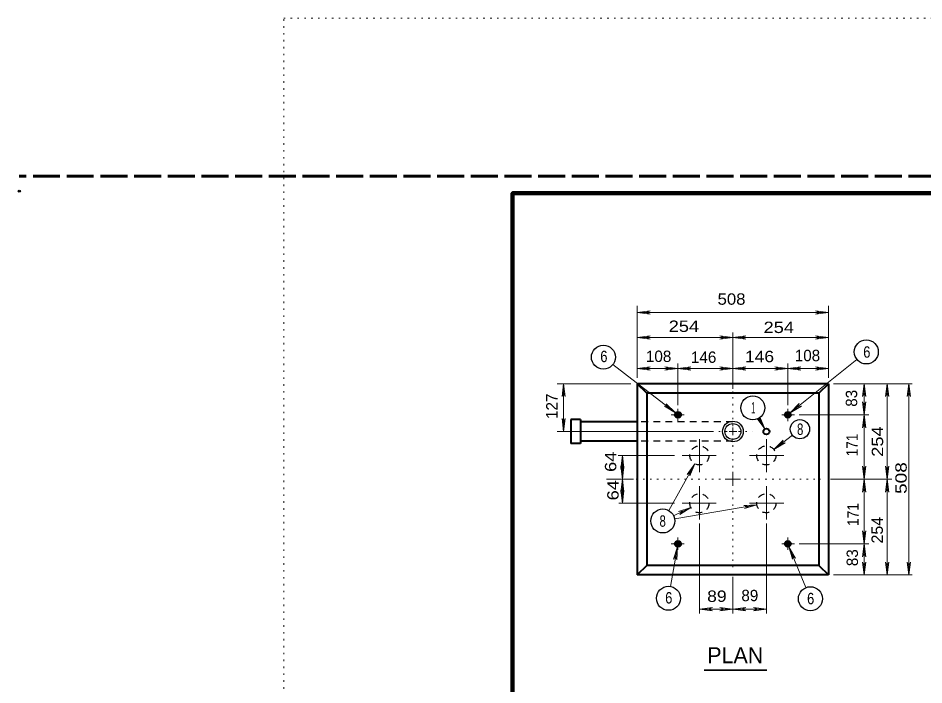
# Model space of a CAD drawing. Extents: x 312583 to 312854, y 144419 to 144597.
# Drawn here: x 312583.5 to 312644, y 144552.2 to 144596.8 of the extents above; entities that cross this region are included whole.
import ezdxf
from ezdxf.enums import TextEntityAlignment as Align

# ---------------------------------------------------------------- set-up
doc = ezdxf.new("R2010")
doc.units = 0
doc.header["$LTSCALE"] = 0.3
doc.header["$PDMODE"] = 32
doc.header["$PDSIZE"] = 0.15
for name, pattern in [('DOTTED', [1.5, 0.3, -1.2]), ('LONG_DASHED', [7.5, 6, -1.5]), ('SHORT_DASHED', [2.7, 1.5, -1.2])]:
    doc.linetypes.add(name, pattern=pattern)
for name, color, linetype, lineweight in [('1', 7, 'Continuous', 25), ('2', 7, 'Continuous', 13), ('63', 7, 'DOTTED', 13)]:
    doc.layers.add(name, color=color, linetype=linetype, lineweight=lineweight)

msp = doc.modelspace()

# ---------------------------------------------------------------- linework, layer by layer
at = {"layer": '1', "linetype": 'LONG_DASHED', "lineweight": 60}
msp.add_line((312851.75, 144586.2246), (312583.526, 144586.2246), dxfattribs=at)
at = {"layer": '1', "lineweight": 40}
for p, q in [((312637.6103, 144572.3614), (312624.83, 144572.3614)), ((312624.83, 144572.3614), (312624.83, 144559.581)), ((312625.4663, 144571.725), (312624.83, 144572.3614)), ((312637.6103, 144572.3614), (312636.9663, 144571.725)), ((312637.6103, 144572.3614), (312637.6103, 144559.581)), ((312636.9663, 144571.725), (312636.9663, 144560.225)), ((312620.3986, 144569.9694), (312620.3986, 144568.367)), ((312621.035, 144569.9694), (312620.3986, 144569.9694)), ((312621.035, 144569.9694), (312621.035, 144568.367)), ((312624.83, 144569.8084), (312621.035, 144569.8084)), ((312621.035, 144568.367), (312620.3986, 144568.367)), ((312624.83, 144568.528), (312621.035, 144568.528)), ((312625.4663, 144560.225), (312624.83, 144559.581)), ((312636.9663, 144560.225), (312625.4663, 144560.225)), ((312636.9663, 144560.225), (312637.6103, 144559.581)), ((312637.6103, 144559.581), (312624.83, 144559.581))]:
    msp.add_line(p, q, dxfattribs=at)
at = {"layer": '1', "linetype": 'SHORT_DASHED'}
for p, q in [((312631.2163, 144569.8084), (312624.83, 144569.8084)), ((312631.2163, 144568.528), (312624.83, 144568.528))]:
    msp.add_line(p, q, dxfattribs=at)
at = {"layer": '1', "lineweight": 158}
msp.add_lwpolyline([(312616.5, 144423.1446), (312616.5, 144585.0846), (312849, 144585.0846)], dxfattribs=at)
at = {"layer": '1', "lineweight": 40}
msp.add_lwpolyline([(312636.9663, 144571.725), (312625.4663, 144571.725), (312625.4663, 144560.225)], dxfattribs=at)
for centre, radius in [((312627.5452, 144570.285), 0.1996), ((312627.5452, 144570.285), 0.1597), ((312627.5452, 144570.285), 0.1278), ((312627.5452, 144570.285), 0.1022), ((312627.5452, 144570.285), 0.0818), ((312627.5452, 144570.285), 0.0654), ((312627.5452, 144570.285), 0.0523), ((312627.5452, 144570.285), 0.0419), ((312627.5452, 144570.285), 0.0335), ((312634.8925, 144570.285), 0.1996), ((312634.8925, 144570.285), 0.1597), ((312634.8925, 144570.285), 0.1278), ((312634.8925, 144570.285), 0.1022), ((312634.8925, 144570.285), 0.0818), ((312634.8925, 144570.285), 0.0654), ((312634.8925, 144570.285), 0.0523), ((312634.8925, 144570.285), 0.0419), ((312634.8925, 144570.285), 0.0335), ((312633.455, 144569.1669), 0.1996), ((312627.5452, 144561.66), 0.1996), ((312627.5452, 144561.66), 0.1597), ((312627.5452, 144561.66), 0.1278), ((312627.5452, 144561.66), 0.1022), ((312627.5452, 144561.66), 0.0818), ((312627.5452, 144561.66), 0.0654), ((312627.5452, 144561.66), 0.0523), ((312627.5452, 144561.66), 0.0419), ((312627.5452, 144561.66), 0.0335), ((312634.8925, 144561.66), 0.1996), ((312634.8925, 144561.66), 0.1597), ((312634.8925, 144561.66), 0.1278), ((312634.8925, 144561.66), 0.1022), ((312634.8925, 144561.66), 0.0818), ((312634.8925, 144561.66), 0.0654), ((312634.8925, 144561.66), 0.0523), ((312634.8925, 144561.66), 0.0419), ((312634.8925, 144561.66), 0.0335)]:
    msp.add_circle(centre, radius, dxfattribs=at)
at = {"layer": '1'}
for radius in [0.6919, 0.5322]:
    msp.add_circle((312631.2189, 144569.1669), radius, dxfattribs=at)
at = {"layer": '1', "linetype": 'SHORT_DASHED'}
for centre in [(312628.9827, 144567.5697), (312633.455, 144567.5697), (312628.9827, 144564.3753), (312633.455, 144564.3753)]:
    msp.add_circle(centre, 0.6389, dxfattribs=at)
at = {"layer": '1'}
msp.add_point((312583.526, 144585.2246), dxfattribs=at)
at = {"layer": '2'}
for p, q in [((312624.83, 144572.7524), (312624.83, 144577.5517)), ((312637.6103, 144572.7524), (312637.6103, 144577.5517)), ((312624.83, 144577.1224), (312625.6963, 144577.2297)), ((312637.6103, 144577.1224), (312624.83, 144577.1224)), ((312624.83, 144577.1224), (312625.6963, 144577.015)), ((312625.6963, 144577.2297), (312625.4203, 144577.1224)), ((312625.6963, 144577.015), (312625.4203, 144577.1224)), ((312636.744, 144577.2297), (312637.02, 144577.1224)), ((312637.6103, 144577.1224), (312636.744, 144577.2297)), ((312636.744, 144577.015), (312637.02, 144577.1224)), ((312637.6103, 144577.1224), (312636.744, 144577.015)), ((312624.83, 144575.451), (312625.6963, 144575.5584)), ((312625.6963, 144575.5584), (312625.4203, 144575.451)), ((312630.35, 144575.5584), (312630.626, 144575.451)), ((312631.2163, 144575.451), (312630.35, 144575.5584)), ((312631.2163, 144572.0164), (312631.2163, 144575.773)), ((312631.2163, 144575.451), (312632.0826, 144575.5584)), ((312632.0826, 144575.5584), (312631.8066, 144575.451)), ((312636.744, 144575.5584), (312637.02, 144575.451)), ((312637.6103, 144575.451), (312636.744, 144575.5584)), ((312624.83, 144575.451), (312625.6963, 144575.3437)), ((312625.6963, 144575.3437), (312625.4203, 144575.451)), ((312630.35, 144575.3437), (312630.626, 144575.451)), ((312631.2163, 144575.451), (312630.35, 144575.3437)), ((312631.2163, 144575.451), (312632.0826, 144575.3437)), ((312632.0826, 144575.3437), (312631.8066, 144575.451)), ((312636.744, 144575.3437), (312637.02, 144575.451)), ((312637.6103, 144575.451), (312636.744, 144575.3437)), ((312627.544, 144570.9354), (312627.544, 144573.703)), ((312634.8963, 144570.9354), (312634.8963, 144573.703)), ((312635.0496, 144570.4064), (312639.5116, 144573.979)), ((312623.2046, 144573.6417), (312627.3906, 144570.4064)), ((312624.83, 144573.3734), (312625.6963, 144573.4807)), ((312627.544, 144573.3734), (312624.83, 144573.3734)), ((312624.83, 144573.3734), (312625.6963, 144573.266)), ((312625.6963, 144573.4807), (312625.4203, 144573.3734)), ((312625.6963, 144573.266), (312625.4203, 144573.3734)), ((312626.6776, 144573.4807), (312626.9536, 144573.3734)), ((312627.544, 144573.3734), (312626.6776, 144573.4807)), ((312626.6776, 144573.266), (312626.9536, 144573.3734)), ((312627.544, 144573.3734), (312626.6776, 144573.266)), ((312627.544, 144573.3734), (312628.4103, 144573.4807)), ((312631.2163, 144573.3734), (312627.544, 144573.3734)), ((312627.544, 144573.3734), (312628.4103, 144573.266)), ((312628.4103, 144573.4807), (312628.1343, 144573.3734)), ((312628.4103, 144573.266), (312628.1343, 144573.3734)), ((312630.35, 144573.4807), (312630.626, 144573.3734)), ((312631.2163, 144573.3734), (312630.35, 144573.4807)), ((312630.35, 144573.266), (312630.626, 144573.3734)), ((312631.2163, 144573.3734), (312630.35, 144573.266)), ((312631.2163, 144573.3734), (312632.0826, 144573.4807)), ((312631.2163, 144573.3734), (312632.0826, 144573.266)), ((312632.0826, 144573.4807), (312631.8066, 144573.3734)), ((312632.0826, 144573.266), (312631.8066, 144573.3734)), ((312634.03, 144573.4807), (312634.306, 144573.3734)), ((312634.8963, 144573.3734), (312634.03, 144573.4807)), ((312634.03, 144573.266), (312634.306, 144573.3734)), ((312634.8963, 144573.3734), (312634.03, 144573.266)), ((312634.8963, 144573.3734), (312635.7626, 144573.4807)), ((312634.8963, 144573.3734), (312635.7626, 144573.266)), ((312635.7626, 144573.4807), (312635.4866, 144573.3734)), ((312635.7626, 144573.266), (312635.4866, 144573.3734)), ((312636.744, 144573.4807), (312637.02, 144573.3734)), ((312637.6103, 144573.3734), (312636.744, 144573.4807)), ((312636.744, 144573.266), (312637.02, 144573.3734)), ((312637.6103, 144573.3734), (312636.744, 144573.266)), ((312624.4083, 144572.3614), (312619.471, 144572.3614)), ((312619.908, 144572.3614), (312619.8006, 144571.495)), ((312619.908, 144569.1644), (312619.908, 144572.3614)), ((312619.908, 144572.3614), (312620.0153, 144571.495)), ((312637.9476, 144572.3614), (312643.2073, 144572.3614)), ((312639.987, 144572.3614), (312639.8796, 144571.495)), ((312639.987, 144572.3614), (312640.0943, 144571.495)), ((312641.5356, 144572.3614), (312641.4283, 144571.495)), ((312641.5356, 144572.3614), (312641.643, 144571.495)), ((312642.9791, 144572.3614), (312642.8718, 144571.495)), ((312642.9791, 144559.581), (312642.9791, 144572.3614)), ((312642.9791, 144572.3614), (312643.0865, 144571.495)), ((312619.8006, 144571.495), (312619.908, 144571.771)), ((312620.0153, 144571.495), (312619.908, 144571.771)), ((312639.8796, 144571.495), (312639.987, 144571.771)), ((312640.0943, 144571.495), (312639.987, 144571.771)), ((312641.4283, 144571.495), (312641.5356, 144571.771)), ((312641.643, 144571.495), (312641.5356, 144571.771)), ((312642.8718, 144571.495), (312642.9791, 144571.771)), ((312643.0865, 144571.495), (312642.9791, 144571.771)), ((312626.6393, 144570.851), (312626.923, 144570.7667)), ((312627.3906, 144570.4064), (312626.6393, 144570.851)), ((312626.7696, 144571.0197), (312626.923, 144570.7667)), ((312627.3906, 144570.4064), (312626.7696, 144571.0197)), ((312627.544, 144569.8544), (312627.544, 144570.69)), ((312634.8963, 144569.8544), (312634.8963, 144570.69)), ((312635.0496, 144570.4064), (312635.6553, 144571.035)), ((312635.0496, 144570.4064), (312635.7933, 144570.8664)), ((312635.6553, 144571.035), (312635.5096, 144570.782)), ((312635.7933, 144570.8664), (312635.5096, 144570.782)), ((312639.8796, 144571.15), (312639.987, 144570.874)), ((312639.987, 144570.2837), (312639.8796, 144571.15)), ((312640.0943, 144571.15), (312639.987, 144570.874)), ((312639.987, 144570.2837), (312640.0943, 144571.15)), ((312619.8006, 144570.0307), (312619.908, 144569.7547)), ((312619.908, 144569.1644), (312619.8006, 144570.0307)), ((312620.0153, 144570.0307), (312619.908, 144569.7547)), ((312619.908, 144569.1644), (312620.0153, 144570.0307)), ((312627.958, 144570.2837), (312627.0993, 144570.2837)), ((312632.834, 144570.0384), (312633.064, 144569.8544)), ((312633.3553, 144569.3407), (312632.834, 144570.0384)), ((312632.949, 144570.0537), (312633.3553, 144569.3407)), ((312633.018, 144570.1457), (312633.064, 144569.8544)), ((312633.3553, 144569.3407), (312633.018, 144570.1457)), ((312634.4823, 144570.2837), (312635.341, 144570.2837)), ((312635.64, 144570.2837), (312640.309, 144570.2837)), ((312639.987, 144570.2837), (312639.8796, 144569.4174)), ((312639.987, 144570.2837), (312640.0943, 144569.4174)), ((312631.2163, 144569.1644), (312631.2163, 144569.425)), ((312639.8796, 144569.4174), (312639.987, 144569.6934)), ((312640.0943, 144569.4174), (312639.987, 144569.6934)), ((312629.798, 144569.1644), (312619.471, 144569.1644)), ((312631.2163, 144569.1644), (312630.9633, 144569.1644)), ((312631.2163, 144569.1644), (312631.477, 144569.1644)), ((312631.2163, 144569.1644), (312631.2163, 144568.9114)), ((312633.961, 144567.9607), (312635.1953, 144568.9267)), ((312628.9853, 144566.4427), (312628.9853, 144568.6584)), ((312633.455, 144566.4427), (312633.455, 144568.6584)), ((312633.961, 144567.9607), (312634.5743, 144568.5817)), ((312633.961, 144567.9607), (312634.7123, 144568.413)), ((312634.5743, 144568.5817), (312634.4286, 144568.3287)), ((312634.7123, 144568.413), (312634.4286, 144568.3287)), ((312627.3063, 144567.5697), (312623.5605, 144567.5697)), ((312623.8333, 144567.5697), (312623.726, 144566.7034)), ((312623.8333, 144567.5697), (312623.9406, 144566.7034)), ((312626.9306, 144563.8897), (312628.671, 144567.01)), ((312630.1046, 144567.5697), (312627.82, 144567.5697)), ((312628.671, 144567.01), (312628.1573, 144566.3047)), ((312628.671, 144567.01), (312628.3413, 144566.205)), ((312632.3356, 144567.5697), (312634.6203, 144567.5697)), ((312623.726, 144566.7034), (312623.8333, 144566.9794)), ((312623.726, 144566.8414), (312623.8333, 144566.5654)), ((312623.8333, 144565.975), (312623.726, 144566.8414)), ((312623.9406, 144566.7034), (312623.8333, 144566.9794)), ((312623.9406, 144566.8414), (312623.8333, 144566.5654)), ((312623.8333, 144565.975), (312623.9406, 144566.8414)), ((312628.1573, 144566.3047), (312628.3796, 144566.4964)), ((312628.3413, 144566.205), (312628.3796, 144566.4964)), ((312631.2163, 144565.975), (312631.2163, 144566.481)), ((312639.8796, 144566.8414), (312639.987, 144566.5654)), ((312639.987, 144565.975), (312639.8796, 144566.8414)), ((312640.0943, 144566.8414), (312639.987, 144566.5654)), ((312639.987, 144565.975), (312640.0943, 144566.8414)), ((312641.4283, 144566.8414), (312641.5356, 144566.5654)), ((312641.5356, 144565.975), (312641.4283, 144566.8414)), ((312641.643, 144566.8414), (312641.5356, 144566.5654)), ((312641.5356, 144565.975), (312641.643, 144566.8414)), ((312624.5693, 144565.975), (312622.776, 144565.975)), ((312623.8333, 144565.975), (312623.726, 144565.1087)), ((312623.8333, 144565.975), (312623.9406, 144565.1087)), ((312631.2163, 144565.975), (312630.7103, 144565.975)), ((312631.2163, 144565.975), (312631.73, 144565.975)), ((312631.2163, 144565.975), (312631.2163, 144565.5457)), ((312637.733, 144565.975), (312641.85, 144565.975)), ((312639.987, 144565.975), (312639.8796, 144565.1087)), ((312639.987, 144565.975), (312640.0943, 144565.1087)), ((312641.5356, 144565.975), (312641.4283, 144565.1087)), ((312641.5356, 144565.975), (312641.643, 144565.1087)), ((312623.726, 144565.1087), (312623.8333, 144565.3847)), ((312623.726, 144565.239), (312623.8333, 144564.963)), ((312623.8333, 144564.3727), (312623.726, 144565.239)), ((312623.9406, 144565.1087), (312623.8333, 144565.3847)), ((312623.9406, 144565.239), (312623.8333, 144564.963)), ((312623.8333, 144564.3727), (312623.9406, 144565.239)), ((312628.9853, 144565.5074), (312628.9853, 144563.284)), ((312633.455, 144565.5074), (312633.455, 144563.284)), ((312639.8796, 144565.1087), (312639.987, 144565.3847)), ((312640.0943, 144565.1087), (312639.987, 144565.3847)), ((312641.4283, 144565.1087), (312641.5356, 144565.3847)), ((312641.643, 144565.1087), (312641.5356, 144565.3847)), ((312627.3063, 144564.3727), (312623.5979, 144564.3727)), ((312627.2603, 144563.537), (312628.4103, 144564.0967)), ((312632.8263, 144564.2654), (312627.3293, 144563.3224)), ((312628.4103, 144564.0967), (312627.5823, 144563.813)), ((312628.4103, 144564.0967), (312627.6743, 144563.6214)), ((312630.1046, 144564.3727), (312627.82, 144564.3727)), ((312632.8263, 144564.2654), (312631.9523, 144564.227)), ((312631.9523, 144564.227), (312632.2436, 144564.1657)), ((312632.8263, 144564.2654), (312631.9906, 144564.0124)), ((312631.9906, 144564.0124), (312632.2436, 144564.1657)), ((312632.3356, 144564.3727), (312634.6203, 144564.3727)), ((312627.5823, 144563.813), (312627.8736, 144563.836)), ((312627.6743, 144563.6214), (312627.8736, 144563.836)), ((312628.9853, 144563.031), (312628.9853, 144557.0127)), ((312633.455, 144563.031), (312633.455, 144557.0127)), ((312639.8796, 144562.525), (312639.987, 144562.249)), ((312639.987, 144561.6587), (312639.8796, 144562.525)), ((312640.0943, 144562.525), (312639.987, 144562.249)), ((312639.987, 144561.6587), (312640.0943, 144562.525)), ((312627.958, 144561.6587), (312627.0993, 144561.6587)), ((312627.544, 144562.0957), (312627.544, 144561.2524)), ((312634.4823, 144561.6587), (312635.341, 144561.6587)), ((312634.8963, 144562.0957), (312634.8963, 144561.2524)), ((312635.64, 144561.6587), (312640.309, 144561.6587)), ((312639.987, 144561.6587), (312639.8796, 144560.7924)), ((312639.987, 144561.6587), (312640.0943, 144560.7924)), ((312627.5133, 144561.467), (312627.0533, 144558.8144)), ((312627.5133, 144561.467), (312627.2603, 144560.6314)), ((312627.5133, 144561.467), (312627.4673, 144560.593)), ((312634.9653, 144561.4747), (312636.0923, 144558.7377)), ((312634.9653, 144561.4747), (312635.1953, 144560.6314)), ((312634.9653, 144561.4747), (312635.3946, 144560.7157)), ((312639.8796, 144560.7924), (312639.987, 144561.0684)), ((312640.0943, 144560.7924), (312639.987, 144561.0684)), ((312627.2603, 144560.6314), (312627.4136, 144560.8844)), ((312627.4673, 144560.593), (312627.4136, 144560.8844)), ((312635.1953, 144560.6314), (312635.1953, 144560.9304)), ((312635.3946, 144560.7157), (312635.1953, 144560.9304)), ((312639.8796, 144560.4474), (312639.987, 144560.1714)), ((312639.987, 144559.581), (312639.8796, 144560.4474)), ((312640.0943, 144560.4474), (312639.987, 144560.1714)), ((312639.987, 144559.581), (312640.0943, 144560.4474)), ((312641.4283, 144560.4474), (312641.5356, 144560.1714)), ((312641.5356, 144559.581), (312641.4283, 144560.4474)), ((312641.643, 144560.4474), (312641.5356, 144560.1714)), ((312641.5356, 144559.581), (312641.643, 144560.4474)), ((312642.8718, 144560.4474), (312642.9791, 144560.1714)), ((312642.9791, 144559.581), (312642.8718, 144560.4474)), ((312643.0865, 144560.4474), (312642.9791, 144560.1714)), ((312642.9791, 144559.581), (312643.0865, 144560.4474)), ((312631.2163, 144559.4584), (312631.2163, 144557.0127)), ((312637.9476, 144559.581), (312643.2073, 144559.581)), ((312628.9853, 144557.304), (312629.8516, 144557.4114)), ((312629.8516, 144557.4114), (312629.5756, 144557.304)), ((312630.35, 144557.4114), (312630.626, 144557.304)), ((312631.2163, 144557.304), (312630.35, 144557.4114)), ((312631.2163, 144557.304), (312632.0826, 144557.4114)), ((312632.0826, 144557.4114), (312631.8066, 144557.304)), ((312632.5886, 144557.4114), (312632.8646, 144557.304)), ((312633.455, 144557.304), (312632.5886, 144557.4114)), ((312628.9853, 144557.304), (312629.8516, 144557.1967)), ((312629.8516, 144557.1967), (312629.5756, 144557.304)), ((312630.35, 144557.1967), (312630.626, 144557.304)), ((312631.2163, 144557.304), (312630.35, 144557.1967)), ((312631.2163, 144557.304), (312632.0826, 144557.1967)), ((312632.0826, 144557.1967), (312631.8066, 144557.304)), ((312632.5886, 144557.1967), (312632.8646, 144557.304)), ((312633.455, 144557.304), (312632.5886, 144557.1967))]:
    msp.add_line(p, q, dxfattribs=at)
at = {"layer": '2', "linetype": 'DOTTED'}
for p, q in [((312631.2163, 144566.7647), (312631.2163, 144571.8477)), ((312631.2163, 144569.678), (312631.2163, 144569.4787)), ((312630.833, 144569.1644), (312629.798, 144569.1644)), ((312631.5996, 144569.1644), (312632.5273, 144569.1644)), ((312630.3806, 144565.975), (312624.5693, 144565.975)), ((312632.006, 144565.975), (312637.0966, 144565.975)), ((312631.2163, 144565.216), (312631.2163, 144560.0947))]:
    msp.add_line(p, q, dxfattribs=at)
at = {"layer": '2', "lineweight": 35}
msp.add_line((312633.4801, 144553.2272), (312629.2959, 144553.2272), dxfattribs=at)
at = {"layer": '2'}
for points in [[(312637.6103, 144575.451), (312631.2163, 144575.451), (312624.83, 144575.451)], [(312637.6103, 144573.3734), (312634.8963, 144573.3734), (312631.2163, 144573.3734)], [(312639.987, 144572.3614), (312639.987, 144570.2837), (312639.987, 144565.975)], [(312641.5356, 144559.581), (312641.5356, 144565.975), (312641.5356, 144572.3614)], [(312623.8333, 144567.5697), (312623.8333, 144565.975), (312623.8333, 144564.3727)], [(312639.987, 144559.581), (312639.987, 144561.6587), (312639.987, 144565.975)], [(312633.455, 144557.304), (312631.2163, 144557.304), (312628.9853, 144557.304)]]:
    msp.add_lwpolyline(points, dxfattribs=at)
at = {"layer": '2', "lineweight": 25}
for centre, radius in [((312622.5664, 144574.133), 0.8026), ((312640.1352, 144574.4831), 0.8026), ((312632.5477, 144570.7475), 0.8026), ((312635.6994, 144569.3177), 0.6421), ((312626.5358, 144563.1888), 0.8026), ((312626.9147, 144558.0234), 0.8026), ((312636.3996, 144557.994), 0.8026)]:
    msp.add_circle(centre, radius, dxfattribs=at)
at = {"layer": '63'}
for p, q in [((312601.2, 144596.7846), (312853.5, 144596.7846)), ((312601.2, 144418.5846), (312601.2, 144596.7846))]:
    msp.add_line(p, q, dxfattribs=at)

# ---------------------------------------------------------------- texts
at = {"layer": '2'}
for s, width, p in [('508', 1.1, (312630.1957, 144577.6363)), ('254 ', 1.2, (312626.9283, 144575.8202)), ('254 ', 1.2, (312633.2673, 144575.7454)), ('6', 0.85, (312639.9297, 144574.0989)), ('6', 0.85, (312622.3576, 144573.8023)), ('146 ', 1.15, (312632.0225, 144573.797)), ('1', 0.5, (312632.4404, 144570.3746)), ('8', 0.75, (312635.5053, 144568.9409)), ('8', 0.75, (312626.3157, 144562.8059)), ('89 ', 1.15, (312629.4991, 144557.7843)), ('6', 0.85, (312626.6936, 144557.6759)), ('6', 0.85, (312636.1772, 144557.6266))]:
    msp.add_text(s, height=0.76, dxfattribs=dict(at, width=width)).set_placement(p)
for s, p in [('108', (312625.4077, 144573.8115)), ('146', (312628.416, 144573.7529)), ('108', (312635.3553, 144573.8644)), ('89', (312631.7859, 144557.831))]:
    msp.add_text(s, height=0.76, dxfattribs=at).set_placement(p)
for s, p in [('83', (312639.5255, 144570.8192)), ('127', (312619.4983, 144570.0035)), ('83', (312639.5772, 144560.1693))]:
    msp.add_text(s, height=0.76, rotation=90, dxfattribs=at).set_placement(p)
for s, width, p in [('254 ', 1.2, (312641.2606, 144567.4769)), ('171', 0.9, (312639.5629, 144567.5018)), ('64 ', 1.2, (312623.4268, 144566.4661)), ('508 ', 1.25, (312642.8348, 144564.9967)), ('64 ', 1.2, (312623.5839, 144564.5657)), ('171', 0.9, (312639.6231, 144562.8575)), ('254', 1.05, (312641.2417, 144561.6851))]:
    msp.add_text(s, height=0.76, rotation=90, dxfattribs=dict(at, width=width)).set_placement(p)
msp.add_text('PLAN', height=1.07, dxfattribs=at).set_placement((312631.3778, 144553.6854), align=Align.CENTER)

doc.saveas('drawing.dxf')
